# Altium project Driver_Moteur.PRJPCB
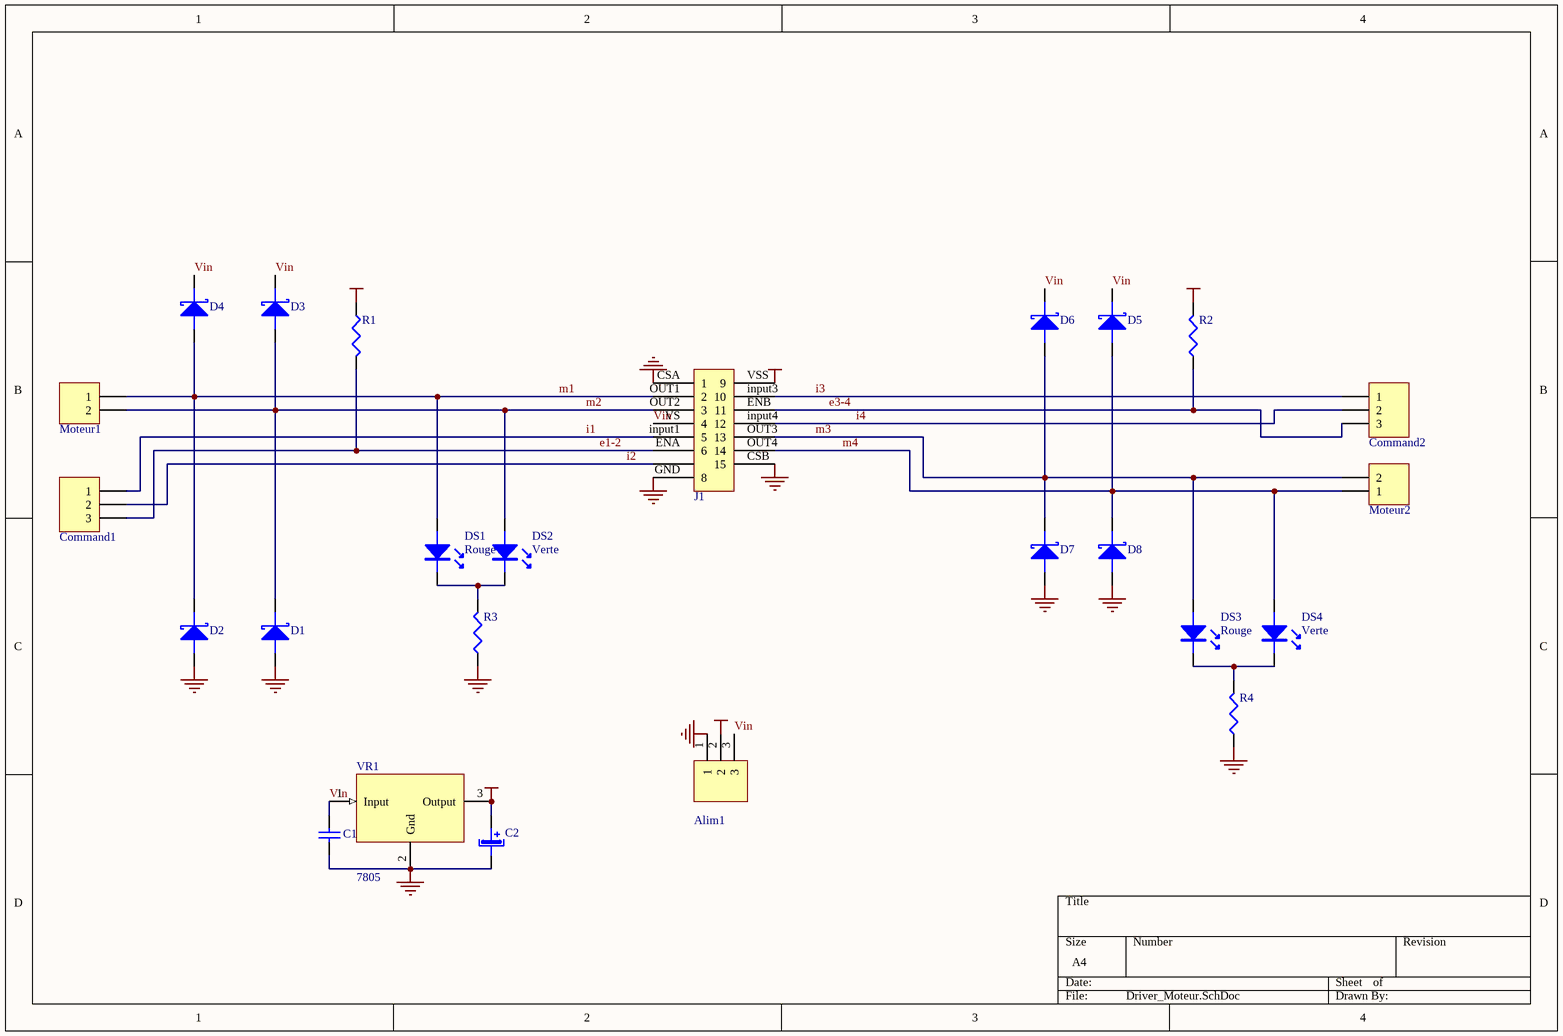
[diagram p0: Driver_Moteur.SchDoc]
1 sheet, 25 parts. Net scope: global (net labels, ports and power ports of the same name join across sheets).
Board file: Driver_Moteur.PcbDoc

## Sheet Driver_Moteur.SchDoc
size A4

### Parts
Alim1  Connecteur 3  [CONVIS-3]  (value not drawn)
C1  Condensateur  [CAPR5.08-7.8x3.2]  (value not drawn)
C2  Cond pol radial  [CAPPR2-5x6.8]  (value not drawn)
Command1  Connecteur 3  [HDR1X3]  (value not drawn)
Command2  Connecteur 3  [HDR1X3]  (value not drawn)
D1  Diode Schottky  [DIODE-0.4]  (value not drawn)
D2  Diode Schottky  [DIODE-0.4]  (value not drawn)
D3  Diode Schottky  [DIODE-0.4]  (value not drawn)
D4  Diode Schottky  [DIODE-0.4]  (value not drawn)
D5  Diode Schottky  [DIODE-0.4]  (value not drawn)
D6  Diode Schottky  [DIODE-0.4]  (value not drawn)
D7  Diode Schottky  [DIODE-0.4]  (value not drawn)
D8  Diode Schottky  [DIODE-0.4]  (value not drawn)
DS1  Color: Rouge  [Led 0.1]  (hidden comment: LED)
DS2  Color: Verte  [Led 0.1]  (hidden comment: LED)
DS3  Color: Rouge  [Led 0.1]  (hidden comment: LED)
DS4  Color: Verte  [Led 0.1]  (hidden comment: LED)
J1  L298  [MultiWatt15]  (value not drawn)
Moteur1  Connecteur 2  [CONVIS-2]  (value not drawn)
Moteur2  Connecteur 2  [CONVIS-2]  (value not drawn)
R1  Résistance  [AXIAL-0.4]  (value not drawn)
R2  Résistance  [AXIAL-0.4]  (value not drawn)
R3  Résistance  [AXIAL-0.4]  (value not drawn)
R4  Résistance  [AXIAL-0.4]  (value not drawn)
VR1  7805  [TO-220 V]

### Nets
+5: Alim1.2 C2.1(+) J1.VSS(9) R1.1 R2.2 VR1.3(Output)
GND: Alim1.1 C1.2 C2.2(-) D1.1(A) D2.1(A) D7.1(A) D8.1(A) J1.CSA(1) J1.CSB(15) J1.GND(8) R3.1 R4.1 VR1.2(Gnd)
e1-2: Command1.3 J1.ENA(6) R1.2
e3-4: Command2.3 J1.ENB(11) R2.1
i1: Command1.1 J1.input1(5)
i2: Command1.2 J1.input2
i3: Command2.1 J1.input3(10)
i4: Command2.2 J1.input4(12)
m1: D2.2(K) D4.1(A) DS1.1(A) J1.OUT1(2) Moteur1.1
m2: D1.2(K) D3.1(A) DS2.1(A) J1.OUT2(3) Moteur1.2
m3: D6.1(A) D7.2(K) DS3.1(A) J1.OUT3(13) Moteur2.2
m4: D5.1(A) D8.2(K) DS4.1(A) J1.OUT4(14) Moteur2.1
Vin: Alim1.3 C1.1 D3.2(K) D4.2(K) D5.2(K) D6.2(K) J1.VS(4) VR1.1(Input)
NetDS1_2: DS1.2(K) DS2.2(K) R3.2
NetDS3_2: DS3.2(K) DS4.2(K) R4.2

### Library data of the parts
Alim1 Command1 Command2 = Connecteur 3: Connecteur
C2 = Cond pol radial: Condensateur polatisé; Type: Condensateur polarisé debout
J1 = L298: Connecteur
Moteur1 Moteur2 = Connecteur 2: Connecteur
R1-R4 = Résistance: Résistance standard
VR1 = 7805: Régulateur 5V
